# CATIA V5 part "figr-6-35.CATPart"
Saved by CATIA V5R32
Part number: Part1
Bounding box of the stored display mesh (mm): x -79 to 0, y -58.176 to 111.436, z 0 to 82.954
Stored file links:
  D:\PROJECTS\Project 2022\CATIA V5 6R 2022\Resources\Part Files\c06_catia_v5_6r2022_prt\figr-6-35.CATPart
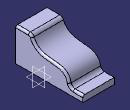
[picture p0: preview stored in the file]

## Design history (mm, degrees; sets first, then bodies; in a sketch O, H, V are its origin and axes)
Body1 (main body)
  Sketch1 on yz-plane, origin (0, 0, 0), H (0, 1, 0), V (0, 0, 1)
    line L1 (111.4359, 0) -> (-58.1761, 0)
    line L2 (-58.1761, 0) -> (-58.1761, 82.9535)
    point P2 (111.4359, 0)
    line L3 (-58.1761, 82.9535) -> (-18.8251, 82.9535)
    point P4 (-18.8251, 82.9535)
    spline S1 through (-18.8251, 82.9535) (0, 57.9624) (68.0293, 40.7554) (77.8618, 15.3546)
    line L4 (77.8618, 15.3546) -> (111.4359, 15.3546)
    line L5 (111.4359, 15.3546) -> (111.4359, 0)
    point P6 (77.8618, 15.3546)
    point P7 (-18.8251, 82.9535)
    point P8 (0, 57.9624)
    point P9 (77.8618, 15.3546)
    horizontal: L1 H, L3 H, L4 H
    vertical: L2 V, L5 V
    coincidence: P2 H, P7 P4, P8 V, P9 P6
  Pad1: profile Sketch1, direction (-1, 0, 0), length 79
  Fillet1: radius 10, on edge [face of Pad1 from Sketch1.S1 | face of Pad1 from Sketch1.L3]; edge [face of Pad1 from Sketch1.L4 | face of Pad1 from Sketch1.S1]
  Fillet2: radius 5, on edge [face of Pad1 from Sketch1.S1 | start face of Pad1]
  Sketch2 on yz-plane, origin (0, 0, 0), H (0, 1, 0), V (0, 0, 1)
    line L1 (-87.2393, 4.8989) -> (80.7003, 4.8989)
